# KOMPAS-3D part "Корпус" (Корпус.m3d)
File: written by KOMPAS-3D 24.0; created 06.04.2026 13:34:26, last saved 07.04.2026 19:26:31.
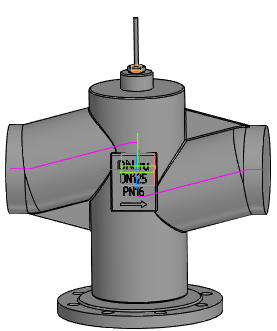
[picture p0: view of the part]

Document properties: Автор: R2D2; Полное имя файла: E:\Работа\Зайцев\Солянка\VSR1-13V-PED-F Клапан запорно-регулирующий DN.ru\DN125\исходные материалы\Корпус.m3d

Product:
- Body: Труба / Нестандартная труба / L = 200.5 мм  | qty 1
    Материал: Нестандартная труба (density 7856 kg/m3)
    Масса: 72.882382
    Раздел спецификации: Детали
    Примечание: 22,54 кг
    additional columns: Pipeline; 0.135; 0; 0; 0.002; 0.20045; true; 0.04
- Body: Труба / Нестандартная труба / L = 200.5 мм  | qty 1
    Материал: Нестандартная труба (density 7856 kg/m3)
    Масса: 72.882382
    Раздел спецификации: Детали
    Форматы листов документа: БЧ
    Примечание: 22,54 кг
    additional columns: Pipeline; 0.135; 0; 0; 0.002; 0.20045; true; 0.04
- Component [standard]: Гайка М16-6H ГОСТ 5916-70  | qty 1  | Масса: 0.01768; Рассекать на разрезах: no; source file: C:\Program Files\ASCON\KOMPAS-3D v24\Libs\PolynomLib\DATA\vault\Methods\Kompas\3D\PLib_Nut_OST92_900.m3d
- Component [standard]: (unnamed)  | qty 1  | Материал: ВЧ40 ГОСТ 7293-85 (density 7200 kg/m3); Масса: 7.029949; Рассекать на разрезах: no; additional columns: 125-16-B-2-ВЧ40-II; Заглушка; ГОСТ 34785-2021
- Body: Тело 4  | qty 1
    Материал: Нестандартная труба (density 7856 kg/m3)
    Масса: 72.882382
- Part/product: Корпус
    Масса: 6.9

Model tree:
1. Эскиз:1
2. Труба:1  (labels: {F703FF30-5BE6-4673-A7F1-8EDA1BE1E2D1}; SHAPEOBJECT3D_ATTR_BUTT; SHAPEOBJECT3D_ATTR_VALID; SHAPEOBJECT3D_ATTR_BUTT_AREA)
     PIPE_R = 7
3. Труба:2  (labels: {F703FF30-5BE6-4673-A7F1-8EDA1BE1E2D1}; SHAPEOBJECT3D_ATTR_BUTT; SHAPEOBJECT3D_ATTR_VALID; SHAPEOBJECT3D_ATTR_BUTT_AREA)
     PIPE_R = 7
4. Эскиз:2
5. Элемент выдавливания:1
     Расстояние 1 = 151; Смещение 1 = -1; Расстояние 2 = 193; Смещение 2 = -5
6. РЕБРО  (with: Ребро.Труба:1, Грань.Элемент выдавливания:1, Грань.Труба:1, Грань.Труба:2)
7. Элемент выдавливания:2
     Расстояние 1 = 8
8. Эскиз:4  (with: Грань.Элемент выдавливания:1)
9. Скругление:3  (with: Ребро.Элемент выдавливания:2)
10. Элемент выдавливания:3
     Расстояние 1 = 1
11. Эскиз:5  (with: Грань.Элемент выдавливания:3)
12. Элемент выдавливания:4
     Расстояние 1 = 7.5; Смещение 1 = 0.5
13. ШТОК
14. Элемент выдавливания:5
15. ОТЛИВКА
16. Скругление:6  (with: Грань.Элемент выдавливания:1)
17. Элемент выдавливания:6  (with: Грань.Элемент выдавливания:1)
     Смещение 1 = 4
18. ТЕКСТ  (with: Грань.Элемент выдавливания:6)
19. Элемент выдавливания:7
     Расстояние 1 = 0.5
20. Скругление:7  (with: Ребро.Элемент выдавливания:6)
     Радиус = 2
21. Эскиз:9  (with: Грань.Элемент выдавливания:1, Ребро.Скругление:6, Ребро.Элемент выдавливания:5)
22. Элемент вращения:1
     Угол 1 = 360
23. Скругление:8  (with: Ребро.Элемент вращения:1, Грань.Элемент выдавливания:3)
     Радиус = 2

Expressions: DS/2+3; v22*2
Referenced files in C:\Program Files\ASCON\KOMPAS-3D v24\Libs\Pipeline\: StylesTemplate.a3d, TemplateHPH, InsulationStylesTemplate.a3d, Insulation
Referenced files in C:\Program Files\ASCON\KOMPAS-3D v24\Templates\: Констр. чертеж А3 гориз. перв. лист.cdt
Referenced files in E:\Работа\Зайцев\Солянка\VSR1-13V-PED-F Клапан запорно-регулирующий DN.ru\DN15\DN15 Kv0.16\исходные материалы\: 
Referenced files in C:\Program Files\ASCON\KOMPAS-3D v24\Libs\PolynomLib\DATA\vault\Methods\Kompas\3D\: PLib_Nut_OST92_900.m3d, PLib_Flange_Blind_GOST_34785_2100.m3d
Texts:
  Отводы ГОСТ 17375-2001
  Констр. чертеж А3 гориз. перв. лист.cdt
  BOSimple***PART:2c8e7818-1586-f79e-db7d-bc045ba468e4***SHORTLOC:Root±30±10±20±©{}110±10±50±80[Нет;Без покрытия;Без указания материала;-;16;2;24]
  BOSimple***Material:38d6725a-5efe-48e1-b177-a7817acb862a
  BOSimple***PART:640df19e-da09-d9fe-181c-97636523b2cc***SHORTLOC:B619_EF039B503CC34112[2;16;125;Круглая;II;ВЧ40 ГОСТ 7293-85]
  var3D
  PN16
  LL-10
  DN+10
  bcut1
  hole1
  hcut1
  hole2
  cut1
  Труба / Нестандартная труба / L = %s мм
  Plane. Начало координат
  Ось Y.Начало координат
  Плоскость ZX.Начало координат
  Горизонтальная плоскость. Начало координат
  Плоскость XY.Начало координат
  Плоскость ZY.Начало координат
